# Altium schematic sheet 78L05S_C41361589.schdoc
size 127 x 101 mm
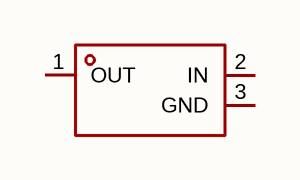
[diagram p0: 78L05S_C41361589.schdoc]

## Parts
U?  78l05s_c41361589  [SOT-23-3_L3.0-W1.7-P0.95-LS2.9-BR]  (value not drawn)

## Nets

Not connected (* = marked no-connect by the designer): U? 1(OUT) 2(IN) 3(GND)

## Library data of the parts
U? = 78l05s_c41361589: 输出极性:正极;工作电压:30V;输出电压:5V;输出电流:100mA;电源纹波抑制比(PSRR):49dB@(120Hz);输出类型:固定;; Manufacturer: JSMSEMI(杰盛微); ManufacturerPart: 78L05S; AddInBom: yes; ModelId: 89cb27a44ab2466697082bb9fd73a7d0; ModelName: SOT-23-3L_L2.9-W1.6-H1.1-LS2.8-P0.95; ModelTransform: 114.173,110.236,0,90,0,0,0,0,0; Output Configuration: 正极; Voltage - Supply: 30V; Output Voltage: 5V; Output Current: 100mA; Voltage Dropout: 1.7V; standby current: 3.8mA; Noise: 42uVrms; Output Type: 固定; Number of Outputs: 1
